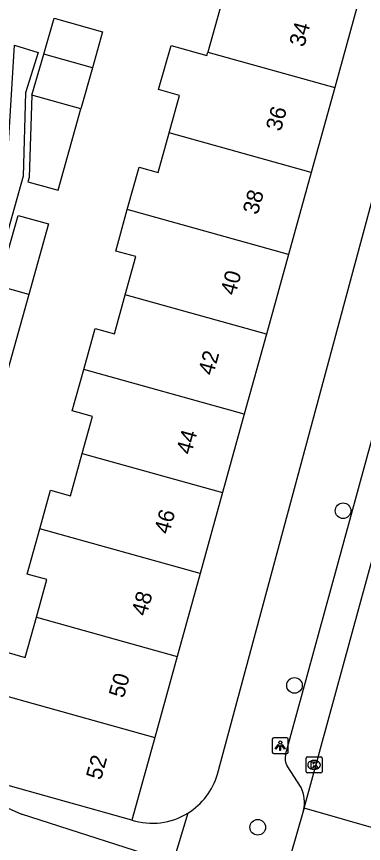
# Model space of a CAD drawing. Extents: x 162542 to 163144, y 380786 to 381511.
# Drawn here: x 163066.5 to 163088.3, y 381021.1 to 381072.9 of the extents above; entities that cross this region are included whole.
import ezdxf

# ---------------------------------------------------------------- set-up
doc = ezdxf.new("R2010")
doc.units = 0
for name, color, linetype in [('IMGEO_Boom', 7, 'Continuous'), ('IMGEO_Kolk', 7, 'Continuous'), ('IMGEO_Lichtpunt', 7, 'Continuous'), ('IMGEO_Pand', 7, 'Continuous'), ('IMGEO_Pand_nummerreeks', 7, 'Continuous'), ('IMGEO_Rijbaan_lokaal_open', 7, 'Continuous'), ('IMGEO_Voetpad_open', 7, 'Continuous')]:
    doc.layers.add(name, color=color, linetype=linetype)

msp = doc.modelspace()

# ---------------------------------------------------------------- linework, layer by layer
at = {"layer": 'IMGEO_Boom'}
for centre in [(163086.994, 381041.913), (163083.949, 381030.975), (163081.642, 381022.087)]:
    msp.add_circle(centre, 0.489, dxfattribs=at)
at = {"layer": 'IMGEO_Kolk'}
for p, q in [((163084.675, 381025.568), (163084.675, 381026.42)), ((163084.75, 381026.494), (163085.602, 381026.494)), ((163085.163, 381026.274), (163085.188, 381026.274)), ((163085.676, 381026.42), (163085.676, 381025.568)), ((163085.186, 381025.714), (163085.161, 381025.714)), ((163085.602, 381025.494), (163084.75, 381025.494))]:
    msp.add_line(p, q, dxfattribs=at)
for points in [[(163084.675, 381025.568), (163084.675, 381026.42)], [(163084.75, 381026.494), (163085.602, 381026.494)], [(163085.676, 381026.42), (163085.676, 381025.568)], [(163084.996, 381026.194), (163085.119, 381026.194), (163085.119, 381026.043), (163085.249, 381026.194), (163085.413, 381026.194), (163085.267, 381026.043), (163085.42, 381025.794), (163085.268, 381025.794), (163085.183, 381025.958), (163085.119, 381025.891), (163085.119, 381025.794), (163084.996, 381025.794), (163084.996, 381026.194)], [(163085.602, 381025.494), (163084.75, 381025.494)]]:
    msp.add_lwpolyline(points, dxfattribs=at)
for centre, start, end in [((163084.752, 381026.418), 91.552, 178.448), ((163084.752, 381026.418), 91.552, 178.448), ((163085.6, 381026.418), 1.552, 88.448), ((163085.6, 381026.418), 1.552, 88.448), ((163084.752, 381025.57), 181.552, 268.448), ((163084.752, 381025.57), 181.552, 268.448), ((163085.6, 381025.57), 271.552, 358.448), ((163085.6, 381025.57), 271.552, 358.448)]:
    msp.add_arc(centre, 0.0765, start, end, dxfattribs=at)
for centre, major_axis, ratio, start_param, end_param in [((163085.162, 381025.994), (-0.387, 0.002), 0.722429, 4.712389, 7.853982), ((163085.187, 381025.994), (-0.39, 0.002), 0.717154, 1.570796, 4.712389)]:
    msp.add_ellipse(centre, major_axis=major_axis, ratio=ratio, start_param=start_param, end_param=end_param, dxfattribs=at)
at = {"layer": 'IMGEO_Lichtpunt'}
for p, q in [((163082.557, 381027.602), (163082.557, 381026.795)), ((163082.557, 381027.602), (163082.557, 381026.795)), ((163083.459, 381027.697), (163082.651, 381027.697)), ((163083.459, 381027.697), (163082.651, 381027.697)), ((163083.553, 381026.795), (163083.553, 381027.602)), ((163083.553, 381026.795), (163083.553, 381027.602)), ((163082.651, 381026.701), (163083.459, 381026.701)), ((163082.651, 381026.701), (163083.459, 381026.701))]:
    msp.add_line(p, q, dxfattribs=at)
for points in [[(163082.931, 381027.266), (163082.97, 381027.238), (163082.782, 381026.976), (163082.744, 381027.003), (163082.931, 381027.266)], [(163083.143, 381027.238), (163083.181, 381027.265), (163083.368, 381027.003), (163083.329, 381026.975), (163083.143, 381027.238)], [(163083.033, 381027.218), (163083.08, 381027.218), (163083.08, 381026.896), (163083.033, 381026.896), (163083.033, 381027.218)]]:
    msp.add_lwpolyline(points, dxfattribs=at)
msp.add_circle((163083.056, 381027.4), 0.0994, dxfattribs=at)
for centre, start, end in [((163082.651, 381027.602), 90, 180), ((163082.651, 381027.602), 90, 180), ((163083.459, 381027.602), 0, 90), ((163083.459, 381027.602), 0, 90), ((163082.651, 381026.795), 180, 270), ((163082.651, 381026.795), 180, 270), ((163083.459, 381026.795), 270, 0), ((163083.459, 381026.795), 270, 360)]:
    msp.add_arc(centre, 0.0946, start, end, dxfattribs=at)
at = {"layer": 'IMGEO_Pand'}
for points in [[(163079.969, 381075.86), (163078.513, 381070.62)], [(163087.931, 381073.647), (163086.476, 381068.406)], [(163068.22, 381070.499), (163068.879, 381072.756), (163071.903, 381071.902), (163071.271, 381069.65)], [(163076.093, 381065.571), (163076.744, 381067.913), (163075.42, 381068.281), (163076.221, 381071.046), (163078.458, 381070.423), (163078.513, 381070.62)], [(163067.474, 381067.945), (163068.22, 381070.499)], [(163071.271, 381069.65), (163068.22, 381070.499)], [(163078.513, 381070.62), (163086.476, 381068.406)], [(163071.271, 381069.65), (163070.552, 381067.089)], [(163086.476, 381068.406), (163085.001, 381063.092)], [(163067.474, 381067.945), (163067.299, 381062.777), (163067.222, 381062.51), (163069.119, 381061.982), (163070.552, 381067.089)], [(163070.552, 381067.089), (163067.474, 381067.945)], [(163073.463, 381060.774), (163074.202, 381063.432), (163075.406, 381063.097), (163076.093, 381065.571)], [(163085.001, 381063.092), (163076.093, 381065.571)], [(163085.001, 381063.092), (163083.577, 381057.961)], [(163065.341, 381056.001), (163066.613, 381060.403), (163068.526, 381059.871), (163067.287, 381055.46)], [(163073.328, 381055.438), (163073.991, 381057.822), (163072.739, 381058.17), (163073.463, 381060.774)], [(163083.577, 381057.961), (163073.463, 381060.774)], [(163083.577, 381057.961), (163082.192, 381052.974)], [(163067.287, 381055.46), (163065.341, 381056.001)], [(163067.287, 381055.46), (163065.941, 381050.665)], [(163070.735, 381050.75), (163071.452, 381053.331), (163072.65, 381052.998), (163073.328, 381055.438)], [(163082.192, 381052.974), (163073.328, 381055.438)], [(163082.192, 381052.974), (163080.799, 381047.953)], [(163070.628, 381045.494), (163071.272, 381047.811), (163070.015, 381048.16), (163070.735, 381050.75)], [(163080.799, 381047.953), (163070.735, 381050.75)], [(163080.799, 381047.953), (163079.436, 381043.045)], [(163067.97, 381040.773), (163068.643, 381043.194), (163069.892, 381042.847), (163070.628, 381045.494)], [(163070.628, 381045.494), (163079.436, 381043.045)], [(163079.436, 381043.045), (163078.029, 381037.977)], [(163067.763, 381035.244), (163068.418, 381037.599), (163067.184, 381037.942), (163067.97, 381040.773)], [(163078.029, 381037.977), (163067.97, 381040.773)], [(163078.029, 381037.977), (163076.589, 381032.786)], [(163065.061, 381030.539), (163065.7, 381032.836), (163065.769, 381033.086), (163067.064, 381032.727), (163067.763, 381035.244)], [(163067.763, 381035.244), (163076.589, 381032.786)], [(163076.589, 381032.786), (163075.182, 381027.72)], [(163065.061, 381030.539), (163075.182, 381027.72)], [(163075.182, 381027.72), (163073.745, 381022.542)], [(163073.745, 381022.542), (163065.074, 381024.953)]]:
    msp.add_lwpolyline(points, dxfattribs=at)
at = {"layer": 'IMGEO_Rijbaan_lokaal_open'}
for points in [[(163084.559, 381023.291), (163102.722, 381089.551)], [(163084.522, 381023.155), (163083.684, 381020.268)], [(163084.559, 381023.291), (163084.522, 381023.155)], [(163089.373, 381021.916), (163084.559, 381023.291)]]:
    msp.add_lwpolyline(points, dxfattribs=at)
at = {"layer": 'IMGEO_Voetpad_open'}
for points in [[(163079.113, 381025.409), (163089.044, 381062.198), (163093.539, 381078.503), (163098.537, 381095.857), (163108.607, 381132.594), (163108.43, 381133.686), (163107.841, 381134.207), (163105.012, 381135.183)], [(163083.391, 381026.615), (163086.585, 381038.264), (163100.487, 381088.976), (163100.631, 381089.497)], [(163065.835, 381062.155), (163066.389, 381071.067), (163067.876, 381070.6), (163067.083, 381068.079), (163066.935, 381062.854), (163060.637, 381040.472)], [(163084.362, 381024.584), (163083.484, 381025.93)], [(163076.311, 381019.863), (163066.831, 381022.9)], [(163077.265, 381022.975), (163076.311, 381019.863)]]:
    msp.add_lwpolyline(points, dxfattribs=at)
for centre, radius, start, end in [((163078.527, 381049.395), 28.962, 217.3359, 246.1806), ((163084.323, 381026.393), 0.958, 166.5902, 208.873), ((163075.038, 381026.585), 4.241, 301.6766, 343.9086), ((163082.389, 381023.64), 2.187, 347.2002, 25.577), ((163075.035, 381026.582), 4.24, 252.293, 301.7326)]:
    msp.add_arc(centre, radius, start, end, dxfattribs=at)

# ---------------------------------------------------------------- texts
at = {"layer": 'IMGEO_Pand_nummerreeks'}
for s, rotation, p in [('34', 74.4845, (163084.554, 381070.904)), ('36', 74.4862, (163083.089, 381065.627)), ('38', 74.4862, (163081.641, 381060.407)), ('40', 74.4862, (163080.236, 381055.348)), ('42', 74.4862, (163078.845, 381050.338)), ('44', 74.4862, (163077.468, 381045.377)), ('46', 74.4862, (163076.084, 381040.389)), ('48', 74.4907, (163074.661, 381035.262)), ('50', 74.4782, (163073.237, 381030.134)), ('52', 74.4896, (163071.813, 381025.005))]:
    msp.add_text(s, height=1, rotation=rotation, dxfattribs=at).set_placement(p)

doc.saveas('drawing.dxf')
